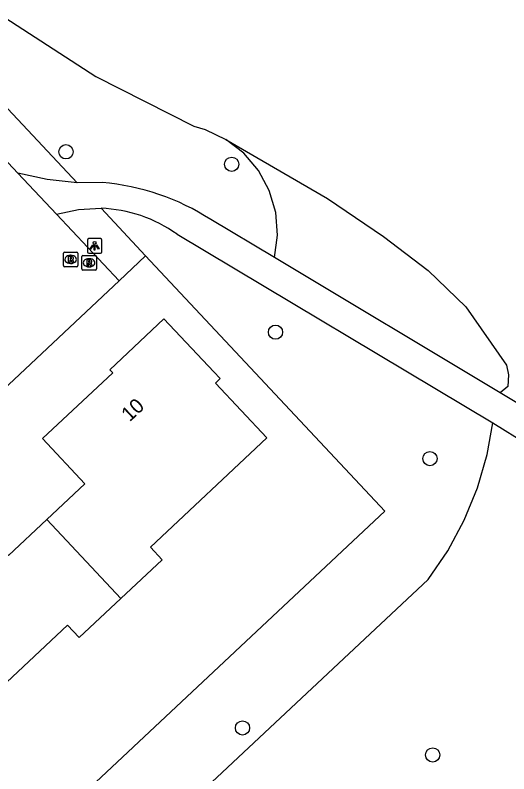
# Model space of a CAD drawing. Extents: x 159353 to 160616, y 385893 to 387321.
# Drawn here: x 160063.3 to 160097.2, y 386296.8 to 386348.8 of the extents above; entities that cross this region are included whole.
import ezdxf

# ---------------------------------------------------------------- set-up
doc = ezdxf.new("R2010")
doc.units = 0
for name, color, linetype in [('IMGEO_Boom', 7, 'Continuous'), ('IMGEO_Groenvoorziening', 7, 'Continuous'), ('IMGEO_Lichtpunt', 7, 'Continuous'), ('IMGEO_Pand', 7, 'Continuous'), ('IMGEO_Pand_nummerreeks', 7, 'Continuous'), ('IMGEO_Rijbaan_lokaal_open', 7, 'Continuous'), ('IMGEO_Rioolput', 7, 'Continuous'), ('IMGEO_Voetpad_halfverhard', 7, 'Continuous')]:
    doc.layers.add(name, color=color, linetype=linetype)

msp = doc.modelspace()

# ---------------------------------------------------------------- linework, layer by layer
at = {"layer": 'IMGEO_Boom'}
for centre in [(160066.752, 386339.46), (160078.128, 386338.606), (160081.137, 386327.084), (160091.735, 386318.412), (160078.868, 386299.935), (160091.925, 386298.085)]:
    msp.add_circle(centre, 0.489, dxfattribs=at)
at = {"layer": 'IMGEO_Groenvoorziening'}
for points in [[(160057.684, 386352.391), (160062.563, 386348.669), (160068.806, 386344.635), (160075.536, 386341.218), (160076.309, 386340.989), (160077.718, 386340.313)], [(160055.245, 386350.409), (160067.508, 386337.34)], [(160077.718, 386340.313), (160084.705, 386336.249), (160088.56, 386333.652), (160091.625, 386331.31), (160094.194, 386328.816), (160096.996, 386324.816), (160097.125, 386324.17), (160097.087, 386323.37), (160096.557, 386322.924)], [(160081.065, 386332.199), (160081.27, 386333.737), (160081.151, 386335.295), (160080.71, 386336.794), (160079.968, 386338.169), (160078.955, 386339.359), (160077.718, 386340.313)], [(160069.157, 386335.582), (160072.216, 386332.322)], [(160072.216, 386332.322), (160088.646, 386314.8), (160061.076, 386288.985)], [(160072.216, 386332.322), (160070.392, 386330.604)], [(160064.793, 386285.015), (160091.616, 386310.114), (160092.961, 386312.09), (160094.093, 386314.196), (160094.998, 386316.409), (160095.667, 386318.704), (160096.066, 386320.856)]]:
    msp.add_lwpolyline(points, dxfattribs=at)
at = {"layer": 'IMGEO_Lichtpunt'}
for p, q in [((160068.22, 386333.407), (160068.22, 386332.6)), ((160068.22, 386333.407), (160068.22, 386332.6)), ((160069.122, 386333.502), (160068.314, 386333.502)), ((160069.122, 386333.502), (160068.314, 386333.502)), ((160069.216, 386332.6), (160069.216, 386333.407)), ((160069.216, 386332.6), (160069.216, 386333.407)), ((160068.314, 386332.506), (160069.122, 386332.506)), ((160068.314, 386332.506), (160069.122, 386332.506))]:
    msp.add_line(p, q, dxfattribs=at)
for points in [[(160068.594, 386333.071), (160068.633, 386333.043), (160068.445, 386332.781), (160068.407, 386332.808), (160068.594, 386333.071)], [(160068.696, 386333.023), (160068.743, 386333.023), (160068.743, 386332.701), (160068.696, 386332.701), (160068.696, 386333.023)], [(160068.806, 386333.043), (160068.844, 386333.07), (160069.031, 386332.808), (160068.992, 386332.78), (160068.806, 386333.043)]]:
    msp.add_lwpolyline(points, dxfattribs=at)
msp.add_circle((160068.719, 386333.205), 0.0994, dxfattribs=at)
for centre, start, end in [((160068.314, 386333.407), 90, 180), ((160068.314, 386333.407), 90, 180), ((160069.122, 386333.407), 0, 90), ((160069.122, 386333.407), 0, 90), ((160068.314, 386332.6), 180, 270), ((160068.314, 386332.6), 180, 270), ((160069.122, 386332.6), 270, 0), ((160069.122, 386332.6), 270, 360)]:
    msp.add_arc(centre, 0.0946, start, end, dxfattribs=at)
at = {"layer": 'IMGEO_Pand'}
for points in [[(160070.514, 386308.807), (160073.355, 386311.47), (160072.547, 386312.33), (160080.547, 386319.828), (160077.015, 386323.595), (160077.343, 386323.902), (160076.907, 386324.364), (160073.478, 386328.003), (160069.765, 386324.513), (160069.966, 386324.307), (160065.146, 386319.783), (160068.048, 386316.682), (160065.428, 386314.229)], [(160065.428, 386314.229), (160062.807, 386311.775), (160059.911, 386314.868), (160055.027, 386310.406), (160054.891, 386310.557), (160051.18, 386307.073), (160054.599, 386303.425), (160055.039, 386302.956), (160055.36, 386303.256), (160058.869, 386299.51), (160066.855, 386306.996), (160067.661, 386306.133), (160070.514, 386308.807)], [(160070.514, 386308.807), (160065.428, 386314.229)]]:
    msp.add_lwpolyline(points, dxfattribs=at)
at = {"layer": 'IMGEO_Rijbaan_lokaal_open'}
for points in [[(160063.444, 386337.995), (160053.282, 386348.81)], [(160063.444, 386337.995), (160066.099, 386335.171)], [(160070.392, 386330.604), (160066.099, 386335.171)], [(160051.119, 386320.747), (160041.959, 386312.146), (160046.09, 386307.804), (160070.392, 386330.604)]]:
    msp.add_lwpolyline(points, dxfattribs=at)
at = {"layer": 'IMGEO_Rioolput'}
for p, q in [((160066.571, 386331.652), (160066.571, 386332.504)), ((160066.646, 386332.578), (160067.498, 386332.578)), ((160067.059, 386332.358), (160067.084, 386332.358)), ((160067.572, 386332.504), (160067.572, 386331.652)), ((160067.835, 386331.421), (160067.835, 386332.273)), ((160067.91, 386332.347), (160068.762, 386332.347)), ((160068.836, 386332.273), (160068.836, 386331.421)), ((160067.082, 386331.798), (160067.057, 386331.798)), ((160068.323, 386332.127), (160068.348, 386332.127)), ((160067.498, 386331.578), (160066.646, 386331.578)), ((160068.762, 386331.347), (160067.91, 386331.347)), ((160068.346, 386331.567), (160068.321, 386331.567))]:
    msp.add_line(p, q, dxfattribs=at)
for points in [[(160066.571, 386331.652), (160066.571, 386332.504)], [(160066.646, 386332.578), (160067.498, 386332.578)], [(160067.16, 386332.276), (160066.908, 386332.278), (160066.908, 386331.878)], [(160067.086, 386332.197), (160067.032, 386332.197), (160067.032, 386332.116)], [(160067.572, 386332.504), (160067.572, 386331.652)], [(160067.835, 386331.421), (160067.835, 386332.273)], [(160067.91, 386332.347), (160068.762, 386332.347)], [(160068.836, 386332.273), (160068.836, 386331.421)], [(160066.908, 386331.878), (160067.032, 386331.878), (160067.032, 386332.04), (160067.043, 386332.04)], [(160067.032, 386332.116), (160067.084, 386332.116)], [(160067.09, 386332.011), (160067.161, 386331.878), (160067.301, 386331.878), (160067.236, 386332.004)], [(160068.424, 386332.045), (160068.172, 386332.047), (160068.172, 386331.647)], [(160068.172, 386331.647), (160068.296, 386331.647), (160068.296, 386331.809), (160068.307, 386331.809)], [(160068.35, 386331.966), (160068.296, 386331.966), (160068.296, 386331.885)], [(160068.296, 386331.885), (160068.348, 386331.885)], [(160068.354, 386331.78), (160068.425, 386331.647), (160068.565, 386331.647), (160068.5, 386331.773)], [(160067.498, 386331.578), (160066.646, 386331.578)], [(160068.762, 386331.347), (160067.91, 386331.347)]]:
    msp.add_lwpolyline(points, dxfattribs=at)
for centre, radius, start, end in [((160066.648, 386332.502), 0.0765, 91.552, 178.448), ((160066.648, 386332.502), 0.0765, 91.552, 178.448), ((160067.092, 386332.101), 0.0964, 77.0061, 93.1865), ((160067.106, 386332.158), 0.0378, 276.6634, 79.6772), ((160067.159, 386332.166), 0.109, 350.3612, 89.416), ((160067.496, 386332.502), 0.0765, 1.552, 88.448), ((160067.496, 386332.502), 0.0765, 1.552, 88.448), ((160067.912, 386332.271), 0.0765, 91.552, 178.448), ((160067.912, 386332.271), 0.0765, 91.552, 178.448), ((160068.76, 386332.271), 0.0765, 1.552, 88.448), ((160068.76, 386332.271), 0.0765, 1.552, 88.448), ((160067.042, 386331.987), 0.0533, 26.0293, 88.6989), ((160067.068, 386332.305), 0.19, 274.7715, 282.9687), ((160067.157, 386332.166), 0.112, 277.5842, 350.9817), ((160067.141, 386331.951), 0.108, 29.5134, 73.7905), ((160068.306, 386331.756), 0.0533, 26.0293, 88.6989), ((160068.332, 386332.074), 0.19, 274.7715, 282.9687), ((160068.356, 386331.87), 0.0964, 77.0061, 93.1865), ((160068.37, 386331.927), 0.0378, 276.6634, 79.6772), ((160068.423, 386331.935), 0.109, 350.3612, 89.416), ((160068.421, 386331.935), 0.112, 277.5842, 350.9817), ((160068.405, 386331.72), 0.108, 29.5134, 73.7905), ((160066.648, 386331.654), 0.0765, 181.552, 268.448), ((160066.648, 386331.654), 0.0765, 181.552, 268.448), ((160067.496, 386331.654), 0.0765, 271.552, 358.448), ((160067.496, 386331.654), 0.0765, 271.552, 358.448), ((160067.912, 386331.423), 0.0765, 181.552, 268.448), ((160067.912, 386331.423), 0.0765, 181.552, 268.448), ((160068.76, 386331.423), 0.0765, 271.552, 358.448), ((160068.76, 386331.423), 0.0765, 271.552, 358.448)]:
    msp.add_arc(centre, radius, start, end, dxfattribs=at)
for centre, major_axis, ratio, start_param, end_param in [((160067.058, 386332.078), (-0.387, 0.002), 0.722429, 4.712389, 7.853982), ((160067.083, 386332.078), (-0.39, 0.002), 0.717154, 1.570796, 4.712389), ((160068.322, 386331.847), (-0.387, 0.002), 0.722429, 4.712389, 7.853982), ((160068.347, 386331.847), (-0.39, 0.002), 0.717154, 1.570796, 4.712389)]:
    msp.add_ellipse(centre, major_axis=major_axis, ratio=ratio, start_param=start_param, end_param=end_param, dxfattribs=at)
at = {"layer": 'IMGEO_Voetpad_halfverhard'}
for points in [[(160067.508, 386337.34), (160065.451, 386337.548), (160063.444, 386337.995)], [(160069.255, 386337.348), (160067.508, 386337.34)], [(160066.099, 386335.171), (160067.622, 386335.51), (160069.157, 386335.582)], [(160081.065, 386332.199), (160076.695, 386334.815)], [(160074.375, 386333.798), (160096.066, 386320.856)], [(160096.557, 386322.924), (160081.065, 386332.199)], [(160119.281, 386309.319), (160118.277, 386309.92), (160096.557, 386322.924)], [(160096.066, 386320.856), (160105.477, 386315.02), (160111.748, 386311.306), (160112.25, 386311.008), (160112.751, 386310.705), (160113.251, 386310.391), (160114.001, 386309.881)]]:
    msp.add_lwpolyline(points, dxfattribs=at)
for centre, radius, start, end in [((160067.856, 386321.047), 16.361, 57.3011, 85.0959), ((160068.834, 386326.115), 9.473, 54.2026, 88.0469)]:
    msp.add_arc(centre, radius, start, end, dxfattribs=at)

# ---------------------------------------------------------------- texts
at = {"layer": 'IMGEO_Pand_nummerreeks'}
msp.add_text('10', height=1, rotation=43.1856, dxfattribs=at).set_placement((160071.123, 386320.894))

doc.saveas('drawing.dxf')
